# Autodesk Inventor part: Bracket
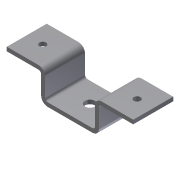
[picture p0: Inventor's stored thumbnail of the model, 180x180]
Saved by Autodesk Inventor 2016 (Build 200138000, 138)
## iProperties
Shininess: 64.0
Length Units: 11269
Angle Units: 11279
Time Units: 11290
Mass Units: 11283
Length Display Precision: 3
Angle Display Precision: 2
Compacted: True
Part Number: Bracket
Document SubType Name: Modeling
Created: 2003-01
Designer: Owner
Density: 1 g/cm^3
Material: Generic
Appearance: Default
Density: 0.0
Volumn: 0.0
Area: 0.0
PropertySet Name: Model Information
Control State: 0
Master: False
Checked Out: False
Author: Owner
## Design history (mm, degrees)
sketch "Sketch2"
  geometry: L1 (487.39, 112.858)-(199.89, 112.858); L2 (199.89, 112.858)-(199.89, -95.142); L3 (199.89, -95.142)-(-175.11, -95.142); L4 (-175.11, -95.142)-(-175.11, 112.858); L5 (-175.11, 112.858)-(-462.61, 112.858); L6 (-462.61, 82.858)-(-205.11, 82.858); L7 (-205.11, 82.858)-(-205.11, -125.142); L8 (-205.11, -125.142)-(229.89, -125.142); L9 (229.89, -125.142)-(229.89, 82.858); L10 (229.89, 82.858)-(487.39, 82.858); L11 (487.39, 112.858)-(487.39, 82.858); L12 (-462.61, 112.858)-(-462.61, 82.858)
  constraints: 24 end point, 5 parallel, 3 perpendicular, 2 collinear, 2 equal length, 1 horizontal, 4 other
  dimensions: "d0" = 375 distance between parallel lines of L4 L2; "d1" = 950 distance of L5.end L1.start; "d2" = 30 distance between parallel lines of L1 L10; "d3" = 238 distance between parallel lines of L5 L8
extrude "Extrusion1" new body sketch "Sketch2" stored distance "d4" = 300; taper "d5" = 0 deg
fillet "Fillet1" dims "d6" = 20
fillet "Fillet2" dims "d7" = 50
sketch "Sketch3"
  geometry: L1 (237.5, 300)-(0, 300) reference; L2 (0, 300)-(0, 0) reference; 1 further point
  dimensions: "d8" = 120 distance from line of L2 point (120, 150); "d9" = 150 distance from line of L1 point (120, 150)
hole "Hole1" sketch "Sketch3" at (120, 150) diameter "d10" = 50; stored, may be unused: countersink angle "d14" = 82 deg, drill point angle "d16" = 118 deg; dims "d11" = 6, "d12" = 4, "d13" = 2, "d15" = 8
pattern_linear "Rectangular Pattern1" dims "d19" = 710
sketch "Sketch4"
  geometry: L1 (0, -300)-(335, -300) reference; 1 further point
  dimensions: "d20" = 150 distance from line of L1 point (167.5, -150)
hole "Hole2" sketch "Sketch4" at (167.5, -150) diameter "d21" = 75; stored, may be unused: countersink angle "d25" = 82 deg, drill point angle "d27" = 118 deg; dims "d22" = 6, "d23" = 4, "d24" = 2, "d26" = 8
body "Solid1"
